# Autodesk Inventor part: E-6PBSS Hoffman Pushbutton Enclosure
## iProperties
Title: E-6PBSS Hoffman Pushbutton Enclosure
Author: S Dotson
Shininess: 0.0
Length Units: 11272
Angle Units: 11286
Time Units: 11279
Mass Units: 11290
Length Display Precision: 4
Angle Display Precision: 2
Compacted: True
PropertySet Name: _Private Model Information
Created: 2001-11
Part Number: Hoffman Pushbutton Enclosure
Material: Steel, Mild
Document SubType Name: Modeling
Designer: S Dotson
Control State: 0
Master: False
Checked Out: False
PropertySet Name: Design Tracking Control
Density: 7.86
Volumn: 94.01930371226516
Area: 815.033447019008
PropertySet Name: Model Information
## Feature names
1. Extrusion3
2. Fillet1
3. Shell1
4. Extrusion4
5. Extrusion6
6. Rectangular Pattern1
7. Extrusion7
8. Extrusion9
9. Extrusion10
10. Fillet4
11. Rectangular Pattern2
12. Mirror1
13. Extrusion11
14. Fillet5
15. Extrusion12
16. Rectangular Pattern3
